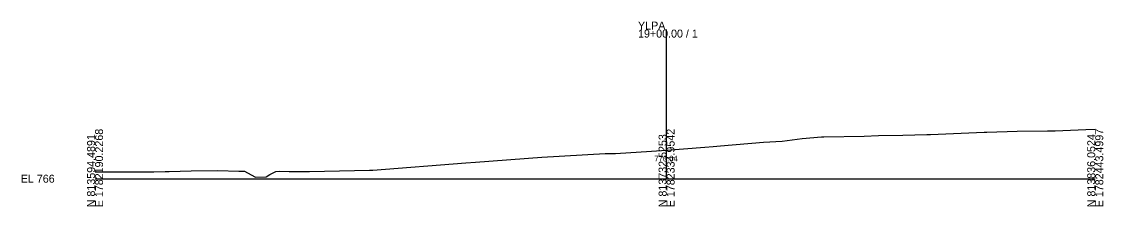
# Model space of a CAD drawing. Extents: x -76 to 1303, y -10 to 9544.
# Drawn here: x -75.7 to 302.8, y 8990.3 to 9055 of the extents above; entities that cross this region are included whole.
import ezdxf

# ---------------------------------------------------------------- set-up
doc = ezdxf.new("R2010")
doc.units = 0
for name, color, linetype in [('Exist Cross Section Cell', 7, 'Continuous'), ('Exist XS Center Line Elevation Label', 7, 'Continuous'), ('Exist XS Ground Line', 7, 'Continuous')]:
    doc.layers.add(name, color=color, linetype=linetype)

msp = doc.modelspace()

# ---------------------------------------------------------------- linework, layer by layer
at = {"layer": 'Exist Cross Section Cell'}
for p, q in [((150, 9000), (150, 9052.23)), ((-50, 9000), (150, 9000)), ((150, 9000), (300, 9000))]:
    msp.add_line(p, q, dxfattribs=at)
at = {"layer": 'Exist XS Ground Line'}
for p, q in [((272.71, 9016.61), (283.34, 9016.77)), ((283.34, 9016.77), (284.6, 9016.78)), ((284.6, 9016.78), (285.94, 9016.8)), ((285.94, 9016.8), (296.75, 9017.2)), ((296.75, 9017.2), (300, 9017.41)), ((183.93, 9012.8), (190.49, 9013.2)), ((190.49, 9013.2), (197.41, 9014.1)), ((197.41, 9014.1), (204.16, 9014.63)), ((204.16, 9014.63), (205.03, 9014.64)), ((205.03, 9014.64), (219.1, 9014.95)), ((219.1, 9014.95), (224.2, 9015.08)), ((224.2, 9015.08), (232.72, 9015.31)), ((232.72, 9015.31), (241.11, 9015.45)), ((241.11, 9015.45), (241.8, 9015.46)), ((241.8, 9015.46), (242.39, 9015.49)), ((242.39, 9015.49), (261.07, 9016.25)), ((261.07, 9016.25), (262.03, 9016.29)), ((262.03, 9016.29), (272.71, 9016.61)), ((132.07, 9008.83), (144.75, 9009.64)), ((144.75, 9009.64), (150, 9010.04)), ((150, 9010.04), (163.39, 9011.07)), ((163.39, 9011.07), (166.29, 9011.31)), ((166.29, 9011.31), (168.85, 9011.48)), ((168.85, 9011.48), (183.93, 9012.8)), ((47.19, 9003.04), (79.75, 9005.59)), ((79.75, 9005.59), (83.13, 9005.76)), ((83.13, 9005.76), (106.34, 9007.51)), ((106.34, 9007.51), (128.45, 9008.83)), ((128.45, 9008.83), (132.07, 9008.83)), ((-50, 9002.44), (-48.18, 9002.39)), ((-48.18, 9002.39), (-46.91, 9002.44)), ((-46.91, 9002.44), (-36.17, 9002.42)), ((-36.17, 9002.42), (-29.49, 9002.43)), ((-29.49, 9002.43), (-25.43, 9002.57)), ((-25.43, 9002.57), (-24.06, 9002.51)), ((-24.06, 9002.51), (-16.31, 9002.76)), ((-16.31, 9002.76), (-7.03, 9002.88)), ((-7.03, 9002.88), (0.34, 9002.67)), ((0.34, 9002.67), (2.28, 9002.59)), ((2.28, 9002.59), (5.93, 9000.65)), ((11.18, 9001.42), (13.25, 9002.57)), ((13.25, 9002.57), (14.42, 9002.7)), ((14.42, 9002.7), (17.91, 9002.56)), ((17.91, 9002.56), (25.01, 9002.5)), ((25.01, 9002.5), (46.02, 9002.99)), ((46.02, 9002.99), (46.62, 9003.02)), ((46.62, 9003.02), (47.19, 9003.04)), ((5.93, 9000.65), (6.3, 9000.51)), ((6.3, 9000.51), (9.84, 9000.66)), ((9.84, 9000.66), (11.18, 9001.42))]:
    msp.add_line(p, q, dxfattribs=at)

# ---------------------------------------------------------------- texts
at = {"layer": 'Exist Cross Section Cell'}
for s, p in [('YLPA', (140, 9052.23)), ('19+00.00 / 1', (140, 9049.43)), ('EL 766', (-76, 8998.6))]:
    msp.add_text(s, height=2.8, dxfattribs=at).set_placement(p)
for s, p in [('E 1782190.2268', (-47.2, 8990)), ('E 1782334.9542', (152.8, 8990)), ('E 1782443.4997', (302.8, 8990)), ('N 813594.4891', (-50, 8990)), ('N 813732.5253', (150, 8990)), ('N 813836.0524', (300, 8990))]:
    msp.add_text(s, height=2.8, rotation=90, dxfattribs=at).set_placement(p)
at = {"layer": 'Exist XS Center Line Elevation Label'}
msp.add_text('776.04', height=2, dxfattribs=at).set_placement((145.72, 9006.04))

doc.saveas('drawing.dxf')
